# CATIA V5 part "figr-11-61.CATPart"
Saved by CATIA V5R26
Part number: Part1
Bounding box of the stored display mesh (mm): x -54 to 54, y -91.936 to 93.838, z -12.649 to 110.643
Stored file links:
  D:\_Deepak\CATIA\CATIA V5-6R2016_Deepak\Resources\Part files\Partfiles\c11_catia_v5_6r2016_prt\figr-11-61.CATPart
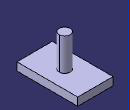
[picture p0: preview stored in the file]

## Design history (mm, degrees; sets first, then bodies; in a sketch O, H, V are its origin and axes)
Set1
  Loft1: Sections (Sketch4; Sketch3)
Body1 (main body)
  Sketch1 on yz-plane, origin (0, 0, 0), H (0, 1, 0), V (0, 0, 1)
    point P1 (93.8379, 11.643)
    line L1 (93.8379, 11.643) -> (93.8379, -12.6487)
    line L2 (93.8379, -12.6487) -> (-91.9362, -12.6487)
    line L3 (-91.9362, -12.6487) -> (-91.9362, 11.643)
    line L4 (-91.9362, 11.643) -> (93.8379, 11.643)
    point P5 (93.8379, 11.643)
    vertical: L1 V, L3 V
    horizontal: L2 H, L4 H
    coincidence: P5 P1
  Pad1: profile Sketch1, direction (1, 0, 0), length 54, mirrored extent
  Sketch2 on face of Pad1, origin (0, 0, 11.643), H (1, 0, 0), V (0, 1, 0)
    circle A1 centre (0, 0) radius 16.7533
    point P1 (16.7533, 0)
    coincidence: A1 P1, P1 H
  Pad2: profile Sketch2, direction (0, 0, 1), length 99
  Sketch3 on face of Pad2, origin (0, 0, 110.643), H (1, 0, 0), V (0, 1, 0)
    point P1 (0, 42.8937)
    point P2 (33.9651, 0)
    projected circle E1 centre (0, 0) radius 16.7533 from edge [face of Pad2 | face of Pad2]
    circle A1 centre (0, 0) radius 33.9651
    point P3 (0, 33.9651)
    coincidence: P1 V, P2 H, A1 P2, A1 P3, P3 V
  Sketch4 on face of Pad1, origin (0, 0, 11.643), H (1, 0, 0), V (0, 1, 0)
    ellipse A1 centre (0, 0) semi-axes 69.9141, 43.1918 rotation 90
    point P1 (0, 69.9141)
    point P2 (43.1918, 0)
    coincidence: P1 V, P2 H, A1 P1, A1 P2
